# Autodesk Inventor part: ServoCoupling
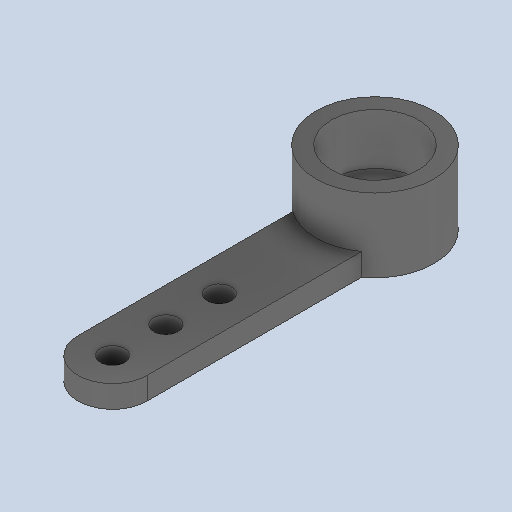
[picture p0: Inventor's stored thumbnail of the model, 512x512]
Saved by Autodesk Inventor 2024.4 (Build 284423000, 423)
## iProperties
Created: 2025-06
Part Number: ServoCoupling
Material: Generic
Document SubType Name: Modeling
Designer: AdminForWorker
Density: 1 g/cm^3
Appearance: Default
Title: ServoCoupling v2
Author: AdminForWorker
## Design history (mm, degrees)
feature "Body1"
body "Solid1"
